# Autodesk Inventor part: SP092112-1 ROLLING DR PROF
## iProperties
Created: 2012-09
Part Number: SP092112-1 ROLLING DR PROF
Material: Aluminum-6061
Description: ROLLING DOOR PROFILE
Document SubType Name: Modeling
Designer: Administrator
Stock Number: 20.1038 ROLLING DOOR PROFILE
Density: 2.71 g/cm^3
Mass: 3476.01 g
Surface Area: 7619.54 cm^2
Volume: 1282.66 cm^3
FINISH: CLEAR ANODIZED
Author: Administrator
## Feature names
1. Extrusion1
2. Hole1
3. Hole2
